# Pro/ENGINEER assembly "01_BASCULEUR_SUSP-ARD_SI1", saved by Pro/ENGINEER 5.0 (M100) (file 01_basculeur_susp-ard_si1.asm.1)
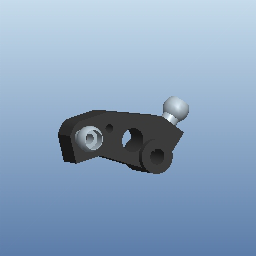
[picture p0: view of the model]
Units: millimeter Newton Second (mmNs); MM, TONNE, HOURS

Other components: 80462200-BASC_AR_TR93_SI1, 80025000-ROTULE_STD_SI1, 80025000-ROTULE_STD_SI1

Other named items: 80462200-BASC_AR_TR93_01, A-DROITE, A-DESSUS, A-FACE, A-R0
